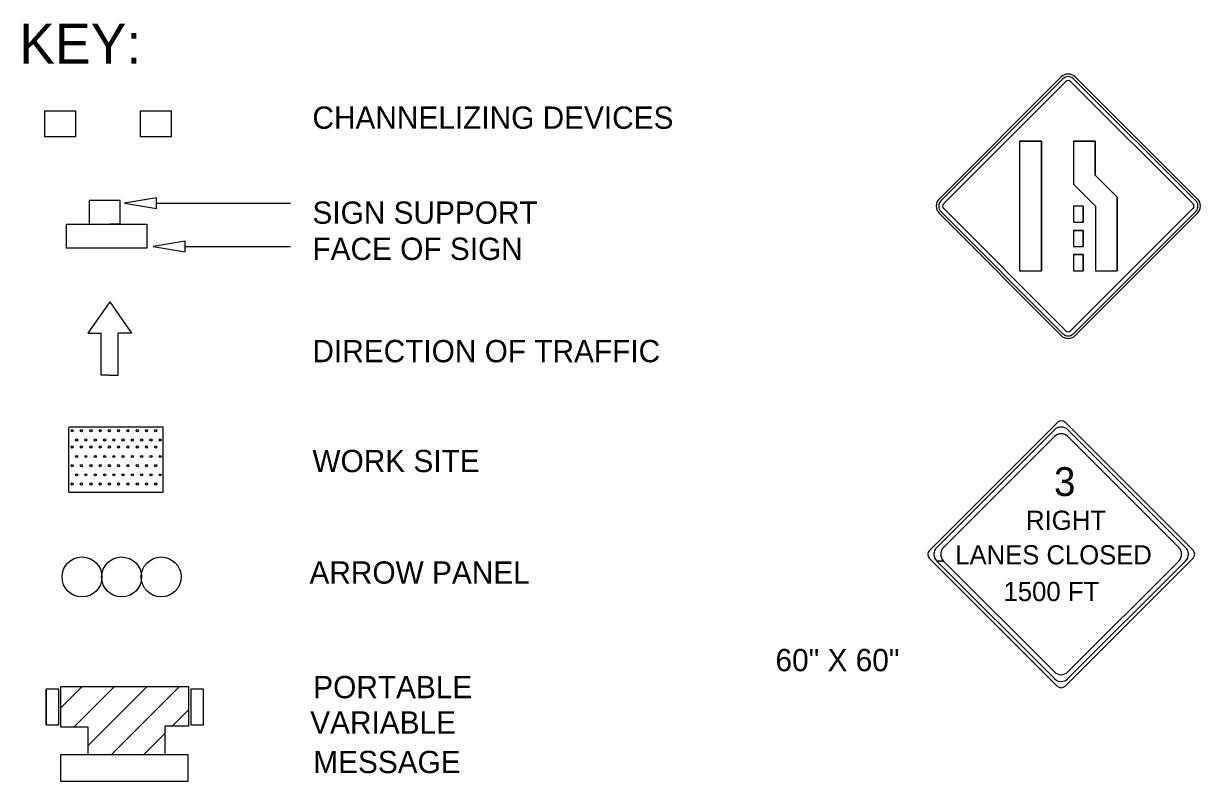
# Model space of a CAD drawing. Extents: x 1531.88 to 1538.58, y 1529.59 to 1539.31.
# Drawn here: x 1531.885 to 1535.053, y 1533.478 to 1535.518 of the extents above; entities that cross this region are included whole.
import ezdxf

# ---------------------------------------------------------------- set-up
doc = ezdxf.new("R2010")
doc.units = 0
for name, color, linetype in [('DETL-DIMS', 7, 'Continuous'), ('DETL-LINE', 7, 'Continuous'), ('DETL-NOTE', 7, 'Continuous'), ('DETL-TITL', 7, 'Continuous'), ('USER-BORD', 7, 'Continuous')]:
    doc.layers.add(name, color=color, linetype=linetype)

# ---------------------------------------------------------------- blocks, each defined once
blk = doc.blocks.new('PANEL0')
at = {"layer": 'USER-BORD'}
for centre in [(0.0309, -0.0012), (0.0928, -0.0012), (0.1546, -0.0012)]:
    blk.add_circle(centre, 0.0312, dxfattribs=at)
blk = doc.blocks.new('DIR2')
at = {"layer": 'USER-BORD'}
for p, q in [((0, 0.0012), (-0.0342, -0.0477)), ((0, 0.0012), (0.0342, -0.0477)), ((-0.0342, -0.0477), (-0.0132, -0.0477)), ((-0.0132, -0.1133), (-0.0132, -0.0477)), ((0.0342, -0.0477), (0.0132, -0.0477)), ((0.0132, -0.1133), (0.0132, -0.0477)), ((-0.0011, -0.1133), (-0.0132, -0.1133)), ((-0.0011, -0.1133), (0.0011, -0.1133)), ((0.0011, -0.1133), (0.0132, -0.1133))]:
    blk.add_line(p, q, dxfattribs=at)
blk = doc.blocks.new('SIGN13')
at = {"layer": 'USER-BORD'}
for points in [[(-0.0134, 0.0182), (0.011, 0.0189), (0.011, 0.0371), (-0.0134, 0.0371)], [(-0.0314, 0.0182), (-0.0314, 0), (0.032, 0), (0.032, 0.0182)]]:
    blk.add_lwpolyline(points, close=True, dxfattribs=at)

msp = doc.modelspace()

# ---------------------------------------------------------------- linework, layer by layer
at = {"layer": 'DETL-DIMS'}
for p, q in [((1532.2428, 1535.0342), (1532.6038, 1535.0342)), ((1532.3199, 1534.9175), (1532.6038, 1534.9175))]:
    msp.add_line(p, q, dxfattribs=at)
for points in [[(1532.2428, 1535.0198), (1532.2428, 1535.0485), (1532.1567, 1535.0342)], [(1532.3199, 1534.9031), (1532.3199, 1534.9319), (1532.2338, 1534.9175)]]:
    msp.add_lwpolyline(points, close=True, dxfattribs=at)
at = {"layer": 'DETL-LINE'}
for p, q in [((1534.3495, 1535.0455), (1534.678, 1535.3741)), ((1534.3543, 1535.0407), (1534.6829, 1535.3692)), ((1534.3619, 1535.0331), (1534.6905, 1535.3616)), ((1534.7036, 1535.3616), (1535.0328, 1535.0331)), ((1534.7112, 1535.3692), (1535.0405, 1535.0407)), ((1534.7161, 1535.3741), (1535.0453, 1535.0455)), ((1534.5663, 1535.2009), (1534.5663, 1534.8522)), ((1534.5663, 1535.2009), (1534.6249, 1535.2009)), ((1534.6249, 1535.2009), (1534.5663, 1535.2009)), ((1534.5663, 1535.2009), (1534.5663, 1534.8522)), ((1534.6249, 1535.2009), (1534.6249, 1534.8522)), ((1534.6249, 1534.8522), (1534.6249, 1535.2009)), ((1534.7114, 1535.2009), (1534.7114, 1535.0858)), ((1534.7114, 1535.2009), (1534.77, 1535.2009)), ((1534.77, 1535.2009), (1534.7114, 1535.2009)), ((1534.7114, 1535.2009), (1534.7114, 1535.0858)), ((1534.77, 1535.2009), (1534.77, 1535.11)), ((1534.77, 1535.11), (1534.77, 1535.2009)), ((1534.8292, 1535.0508), (1534.77, 1535.11)), ((1534.8292, 1535.0508), (1534.77, 1535.11)), ((1534.7706, 1535.0265), (1534.7114, 1535.0858)), ((1534.7114, 1535.0858), (1534.7706, 1535.0265)), ((1534.8292, 1535.0508), (1534.8292, 1534.8522)), ((1534.8292, 1534.8522), (1534.8292, 1535.0508)), ((1534.6829, 1534.6831), (1534.3543, 1535.0123)), ((1534.6905, 1534.6907), (1534.3619, 1535.0199)), ((1535.0328, 1535.0199), (1534.7036, 1534.6907)), ((1535.0405, 1535.0123), (1534.7112, 1534.6831)), ((1534.7114, 1535.0265), (1534.7114, 1534.9829)), ((1534.7373, 1535.0265), (1534.7114, 1535.0265)), ((1534.7114, 1535.0265), (1534.7114, 1534.9829)), ((1534.7373, 1535.0265), (1534.7373, 1534.9829)), ((1534.7373, 1534.9829), (1534.7373, 1535.0265)), ((1534.7706, 1535.0265), (1534.7706, 1534.8522)), ((1534.7706, 1535.0265), (1534.7706, 1534.8522)), ((1534.678, 1534.6783), (1534.3495, 1535.0075)), ((1534.7114, 1534.9829), (1534.7373, 1534.9829)), ((1534.7114, 1534.9829), (1534.7373, 1534.9829)), ((1535.0453, 1535.0075), (1534.7161, 1534.6783)), ((1534.7114, 1534.9611), (1534.7373, 1534.9611)), ((1534.7114, 1534.9611), (1534.7114, 1534.9176)), ((1534.7373, 1534.9611), (1534.7114, 1534.9611)), ((1534.7114, 1534.9611), (1534.7114, 1534.9176)), ((1534.7373, 1534.9611), (1534.7373, 1534.9176)), ((1534.7373, 1534.9176), (1534.7373, 1534.9611)), ((1534.7114, 1534.9176), (1534.7373, 1534.9176)), ((1534.7114, 1534.9176), (1534.7373, 1534.9176)), ((1534.7114, 1534.8958), (1534.7373, 1534.8958)), ((1534.7114, 1534.8958), (1534.7114, 1534.8522)), ((1534.7373, 1534.8958), (1534.7114, 1534.8958)), ((1534.7114, 1534.8958), (1534.7114, 1534.8522)), ((1534.7373, 1534.8958), (1534.7373, 1534.8522)), ((1534.7373, 1534.8522), (1534.7373, 1534.8958)), ((1534.5663, 1534.8522), (1534.6249, 1534.8522)), ((1534.5663, 1534.8522), (1534.6249, 1534.8522)), ((1534.7114, 1534.8522), (1534.7373, 1534.8522)), ((1534.7114, 1534.8522), (1534.7373, 1534.8522)), ((1534.7706, 1534.8522), (1534.8292, 1534.8522)), ((1534.7706, 1534.8522), (1534.8292, 1534.8522)), ((1534.6682, 1534.4439), (1534.3239, 1534.0996)), ((1535.0331, 1534.1003), (1534.6896, 1534.4439)), ((1532.2605, 1534.431), (1532.0065, 1534.431)), ((1532.2605, 1534.431), (1532.0065, 1534.431)), ((1532.2605, 1534.431), (1532.0065, 1534.431)), ((1532.2605, 1534.431), (1532.0065, 1534.431)), ((1532.0066, 1534.2569), (1532.0066, 1534.4309)), ((1532.0066, 1534.2569), (1532.0066, 1534.4309)), ((1532.0151, 1534.4221), (1532.0151, 1534.4221)), ((1532.0159, 1534.4221), (1532.0159, 1534.4221)), ((1532.0407, 1534.4221), (1532.0407, 1534.4221)), ((1532.0407, 1534.4221), (1532.0407, 1534.4221)), ((1532.0655, 1534.4221), (1532.0655, 1534.4221)), ((1532.0663, 1534.4221), (1532.0663, 1534.4221)), ((1532.0903, 1534.4221), (1532.0903, 1534.4221)), ((1532.0911, 1534.4221), (1532.0911, 1534.4221)), ((1532.1151, 1534.4221), (1532.1151, 1534.4221)), ((1532.1159, 1534.4221), (1532.1159, 1534.4221)), ((1532.1407, 1534.4221), (1532.1407, 1534.4221)), ((1532.1407, 1534.4221), (1532.1407, 1534.4221)), ((1532.1655, 1534.4221), (1532.1655, 1534.4221)), ((1532.1655, 1534.4221), (1532.1655, 1534.4221)), ((1532.1903, 1534.4221), (1532.1903, 1534.4221)), ((1532.1911, 1534.4221), (1532.1911, 1534.4221)), ((1532.2151, 1534.4221), (1532.2151, 1534.4221)), ((1532.2159, 1534.4221), (1532.2159, 1534.4221)), ((1532.2407, 1534.4221), (1532.2407, 1534.4221)), ((1532.2407, 1534.4221), (1532.2407, 1534.4221)), ((1532.2605, 1534.257), (1532.2605, 1534.431)), ((1532.2605, 1534.257), (1532.2605, 1534.431)), ((1532.2605, 1534.257), (1532.2605, 1534.431)), ((1532.2605, 1534.257), (1532.2605, 1534.431)), ((1534.6599, 1534.4243), (1534.3432, 1534.1076)), ((1535.013, 1534.1076), (1534.6964, 1534.4243)), ((1532.0151, 1534.3783), (1532.0151, 1534.3783)), ((1532.0159, 1534.3783), (1532.0159, 1534.3783)), ((1532.0279, 1534.3973), (1532.0279, 1534.3973)), ((1532.0279, 1534.3973), (1532.0279, 1534.3973)), ((1532.0407, 1534.3783), (1532.0407, 1534.3783)), ((1532.0407, 1534.3783), (1532.0407, 1534.3783)), ((1532.0527, 1534.3973), (1532.0527, 1534.3973)), ((1532.0527, 1534.3973), (1532.0527, 1534.3973)), ((1532.0655, 1534.3783), (1532.0655, 1534.3783)), ((1532.0663, 1534.3783), (1532.0663, 1534.3783)), ((1532.0783, 1534.3973), (1532.0783, 1534.3973)), ((1532.0783, 1534.3973), (1532.0783, 1534.3973)), ((1532.0903, 1534.3783), (1532.0903, 1534.3783)), ((1532.0911, 1534.3783), (1532.0911, 1534.3783)), ((1532.1031, 1534.3973), (1532.1031, 1534.3973)), ((1532.1031, 1534.3973), (1532.1031, 1534.3973)), ((1532.1151, 1534.3783), (1532.1151, 1534.3783)), ((1532.1159, 1534.3783), (1532.1159, 1534.3783)), ((1532.1279, 1534.3973), (1532.1279, 1534.3973)), ((1532.1279, 1534.3973), (1532.1279, 1534.3973)), ((1532.1407, 1534.3783), (1532.1407, 1534.3783)), ((1532.1407, 1534.3783), (1532.1407, 1534.3783)), ((1532.1527, 1534.3973), (1532.1527, 1534.3973)), ((1532.1527, 1534.3973), (1532.1527, 1534.3973)), ((1532.1655, 1534.3783), (1532.1655, 1534.3783)), ((1532.1655, 1534.3783), (1532.1655, 1534.3783)), ((1532.1775, 1534.3973), (1532.1775, 1534.3973)), ((1532.1775, 1534.3973), (1532.1775, 1534.3973)), ((1532.1903, 1534.3783), (1532.1903, 1534.3783)), ((1532.1911, 1534.3783), (1532.1911, 1534.3783)), ((1532.2031, 1534.3973), (1532.2031, 1534.3973)), ((1532.2031, 1534.3973), (1532.2031, 1534.3973)), ((1532.2151, 1534.3783), (1532.2151, 1534.3783)), ((1532.2159, 1534.3783), (1532.2159, 1534.3783)), ((1532.2279, 1534.3973), (1532.2279, 1534.3973)), ((1532.2279, 1534.3973), (1532.2279, 1534.3973)), ((1532.2407, 1534.3783), (1532.2407, 1534.3783)), ((1532.2407, 1534.3783), (1532.2407, 1534.3783)), ((1532.2527, 1534.3973), (1532.2527, 1534.3973)), ((1532.2527, 1534.3973), (1532.2527, 1534.3973)), ((1534.3614, 1534.1077), (1534.6598, 1534.406)), ((1534.6964, 1534.406), (1534.9948, 1534.1076)), ((1532.0279, 1534.3527), (1532.0279, 1534.3527)), ((1532.0527, 1534.3527), (1532.0527, 1534.3527)), ((1532.0783, 1534.3527), (1532.0783, 1534.3527)), ((1532.1031, 1534.3527), (1532.1031, 1534.3527)), ((1532.1279, 1534.3527), (1532.1279, 1534.3527)), ((1532.1527, 1534.3527), (1532.1527, 1534.3527)), ((1532.1775, 1534.3527), (1532.1775, 1534.3527)), ((1532.2031, 1534.3527), (1532.2031, 1534.3527)), ((1532.2279, 1534.3527), (1532.2279, 1534.3527)), ((1532.2527, 1534.3527), (1532.2527, 1534.3527)), ((1532.0151, 1534.3279), (1532.0151, 1534.3279)), ((1532.0159, 1534.3279), (1532.0159, 1534.3279)), ((1532.0407, 1534.3279), (1532.0407, 1534.3279)), ((1532.0407, 1534.3279), (1532.0407, 1534.3279)), ((1532.0655, 1534.3279), (1532.0655, 1534.3279)), ((1532.0663, 1534.3279), (1532.0663, 1534.3279)), ((1532.0903, 1534.3279), (1532.0903, 1534.3279)), ((1532.0911, 1534.3279), (1532.0911, 1534.3279)), ((1532.1151, 1534.3279), (1532.1151, 1534.3279)), ((1532.1159, 1534.3279), (1532.1159, 1534.3279)), ((1532.1407, 1534.3279), (1532.1407, 1534.3279)), ((1532.1407, 1534.3279), (1532.1407, 1534.3279)), ((1532.1655, 1534.3279), (1532.1655, 1534.3279)), ((1532.1655, 1534.3279), (1532.1655, 1534.3279)), ((1532.1903, 1534.3279), (1532.1903, 1534.3279)), ((1532.1911, 1534.3279), (1532.1911, 1534.3279)), ((1532.2151, 1534.3279), (1532.2151, 1534.3279)), ((1532.2159, 1534.3279), (1532.2159, 1534.3279)), ((1532.2407, 1534.3279), (1532.2407, 1534.3279)), ((1532.2407, 1534.3279), (1532.2407, 1534.3279)), ((1532.0279, 1534.3031), (1532.0279, 1534.3031)), ((1532.0279, 1534.3031), (1532.0279, 1534.3031)), ((1532.0527, 1534.3031), (1532.0527, 1534.3031)), ((1532.0527, 1534.3031), (1532.0527, 1534.3031)), ((1532.0783, 1534.3031), (1532.0783, 1534.3031)), ((1532.0783, 1534.3031), (1532.0783, 1534.3031)), ((1532.1031, 1534.3031), (1532.1031, 1534.3031)), ((1532.1031, 1534.3031), (1532.1031, 1534.3031)), ((1532.1279, 1534.3031), (1532.1279, 1534.3031)), ((1532.1279, 1534.3031), (1532.1279, 1534.3031)), ((1532.1527, 1534.3031), (1532.1527, 1534.3031)), ((1532.1527, 1534.3031), (1532.1527, 1534.3031)), ((1532.1775, 1534.3031), (1532.1775, 1534.3031)), ((1532.1775, 1534.3031), (1532.1775, 1534.3031)), ((1532.2031, 1534.3031), (1532.2031, 1534.3031)), ((1532.2031, 1534.3031), (1532.2031, 1534.3031)), ((1532.2279, 1534.3031), (1532.2279, 1534.3031)), ((1532.2279, 1534.3031), (1532.2279, 1534.3031)), ((1532.2527, 1534.3031), (1532.2527, 1534.3031)), ((1532.2527, 1534.3031), (1532.2527, 1534.3031)), ((1532.0066, 1534.2569), (1532.2606, 1534.2569)), ((1532.0151, 1534.2787), (1532.0151, 1534.2787)), ((1532.0159, 1534.2787), (1532.0159, 1534.2787)), ((1532.0407, 1534.2787), (1532.0407, 1534.2787)), ((1532.0407, 1534.2787), (1532.0407, 1534.2787)), ((1532.0655, 1534.2787), (1532.0655, 1534.2787)), ((1532.0663, 1534.2787), (1532.0663, 1534.2787)), ((1532.0903, 1534.2787), (1532.0903, 1534.2787)), ((1532.0911, 1534.2787), (1532.0911, 1534.2787)), ((1532.1151, 1534.2787), (1532.1151, 1534.2787)), ((1532.1159, 1534.2787), (1532.1159, 1534.2787)), ((1532.1407, 1534.2787), (1532.1407, 1534.2787)), ((1532.1407, 1534.2787), (1532.1407, 1534.2787)), ((1532.1655, 1534.2787), (1532.1655, 1534.2787)), ((1532.1655, 1534.2787), (1532.1655, 1534.2787)), ((1532.1903, 1534.2787), (1532.1903, 1534.2787)), ((1532.1911, 1534.2787), (1532.1911, 1534.2787)), ((1532.2151, 1534.2787), (1532.2151, 1534.2787)), ((1532.2159, 1534.2787), (1532.2159, 1534.2787)), ((1532.2407, 1534.2787), (1532.2407, 1534.2787)), ((1532.2407, 1534.2787), (1532.2407, 1534.2787)), ((1534.3239, 1534.0783), (1534.6675, 1533.7347)), ((1534.3614, 1534.0711), (1534.3432, 1534.0711)), ((1534.3432, 1534.0711), (1534.6599, 1533.7545)), ((1534.3432, 1534.0711), (1534.3614, 1534.0711)), ((1534.6598, 1533.7727), (1534.3614, 1534.0711)), ((1534.6888, 1533.7347), (1535.0331, 1534.079)), ((1534.6964, 1533.7545), (1535.013, 1534.0711)), ((1534.9948, 1534.0711), (1534.6964, 1533.7727)), ((1534.6598, 1533.7727), (1534.6598, 1533.7727)), ((1531.9462, 1533.6301), (1531.9462, 1533.7259)), ((1531.9462, 1533.7259), (1531.9462, 1533.6301)), ((1531.9798, 1533.7259), (1531.9462, 1533.7259)), ((1531.9462, 1533.7259), (1531.9462, 1533.6301)), ((1531.9798, 1533.6301), (1531.9798, 1533.7259)), ((1531.9852, 1533.6762), (1532.0426, 1533.7337)), ((1531.9852, 1533.6243), (1531.9852, 1533.7337)), ((1531.9868, 1533.7337), (1532.3289, 1533.7337)), ((1532.0207, 1533.6243), (1532.13, 1533.7337)), ((1532.0587, 1533.575), (1532.2174, 1533.7337)), ((1532.1217, 1533.5506), (1532.3048, 1533.7337)), ((1532.3289, 1533.7337), (1532.3289, 1533.6262)), ((1532.3689, 1533.7259), (1532.3353, 1533.7259)), ((1532.3353, 1533.7259), (1532.3353, 1533.6301)), ((1532.3689, 1533.6301), (1532.3689, 1533.7259)), ((1532.2848, 1533.6263), (1532.3289, 1533.6705)), ((1531.9462, 1533.6301), (1531.9798, 1533.6301)), ((1532.0587, 1533.6243), (1531.9852, 1533.6243)), ((1532.0587, 1533.5501), (1532.0587, 1533.6243)), ((1532.265, 1533.6262), (1532.265, 1533.5501)), ((1532.3289, 1533.6262), (1532.265, 1533.6262)), ((1532.3353, 1533.6301), (1532.3689, 1533.6301)), ((1532.2091, 1533.5506), (1532.265, 1533.6065)), ((1531.9852, 1533.5501), (1532.3274, 1533.5501)), ((1531.9852, 1533.4778), (1531.9852, 1533.5501)), ((1532.3274, 1533.5501), (1532.3274, 1533.4778)), ((1532.3274, 1533.4778), (1531.9852, 1533.4778))]:
    msp.add_line(p, q, dxfattribs=at)
for points in [[(1531.9423, 1535.2131), (1531.9423, 1535.2826), (1532.0249, 1535.2826), (1532.0249, 1535.2131)], [(1532.1994, 1535.2131), (1532.1994, 1535.2826), (1532.2819, 1535.2826), (1532.2819, 1535.2131)]]:
    msp.add_lwpolyline(points, close=True, dxfattribs=at)
for centre in [(1532.0159, 1534.4219), (1532.0407, 1534.4219), (1532.0663, 1534.4219), (1532.0911, 1534.4219), (1532.1159, 1534.4219), (1532.1407, 1534.4219), (1532.1655, 1534.4219), (1532.1911, 1534.4219), (1532.2159, 1534.4219), (1532.2407, 1534.4219), (1532.0159, 1534.3782), (1532.0279, 1534.3971), (1532.0407, 1534.3782), (1532.0527, 1534.3971), (1532.0663, 1534.3782), (1532.0783, 1534.3971), (1532.0911, 1534.3782), (1532.1031, 1534.3971), (1532.1159, 1534.3782), (1532.1279, 1534.3971), (1532.1407, 1534.3782), (1532.1527, 1534.3971), (1532.1655, 1534.3782), (1532.1775, 1534.3971), (1532.1911, 1534.3782), (1532.2031, 1534.3971), (1532.2159, 1534.3782), (1532.2279, 1534.3971), (1532.2407, 1534.3782), (1532.2527, 1534.3971), (1532.0279, 1534.3526), (1532.0527, 1534.3526), (1532.0783, 1534.3526), (1532.1031, 1534.3526), (1532.1279, 1534.3526), (1532.1527, 1534.3526), (1532.1775, 1534.3526), (1532.2031, 1534.3526), (1532.2279, 1534.3526), (1532.2527, 1534.3526), (1532.0159, 1534.3278), (1532.0407, 1534.3278), (1532.0663, 1534.3278), (1532.0911, 1534.3278), (1532.1159, 1534.3278), (1532.1407, 1534.3278), (1532.1655, 1534.3278), (1532.1911, 1534.3278), (1532.2159, 1534.3278), (1532.2407, 1534.3278), (1532.0159, 1534.2786), (1532.0279, 1534.303), (1532.0407, 1534.2786), (1532.0527, 1534.303), (1532.0663, 1534.2786), (1532.0783, 1534.303), (1532.0911, 1534.2786), (1532.1031, 1534.303), (1532.1159, 1534.2786), (1532.1279, 1534.303), (1532.1407, 1534.2786), (1532.1527, 1534.303), (1532.1655, 1534.2786), (1532.1775, 1534.303), (1532.1911, 1534.2786), (1532.2031, 1534.303), (1532.2159, 1534.2786), (1532.2279, 1534.303), (1532.2407, 1534.2786), (1532.2527, 1534.303)]:
    msp.add_circle(centre, 0.00291, dxfattribs=at)
for centre, radius, start, end in [((1534.697, 1535.3549), 0.027, 45.06, 135), ((1534.697, 1535.3553), 0.0199, 45.06, 135), ((1534.697, 1535.3555), 0.00901, 45.06, 135), ((1534.3687, 1535.0265), 0.027, 135, 224.9399), ((1535.0261, 1535.0265), 0.027, 315, 45.0601), ((1534.3683, 1535.0265), 0.0199, 135, 224.9399), ((1534.3681, 1535.0265), 0.00901, 135, 224.9399), ((1535.0267, 1535.0265), 0.00901, 315, 45.0601), ((1535.0265, 1535.0265), 0.0199, 315, 45.0601), ((1534.697, 1534.6974), 0.027, 224.94, 315), ((1534.697, 1534.697), 0.0199, 224.94, 315), ((1534.697, 1534.6969), 0.00901, 224.94, 315), ((1534.6789, 1534.4333), 0.0151, 45, 135), ((1534.6781, 1534.3878), 0.0258, 45, 135), ((1534.6781, 1534.406), 0.0258, 45, 135), ((1534.3345, 1534.0889), 0.0151, 135, 225), ((1534.3615, 1534.0894), 0.0258, 135, 225), ((1534.3797, 1534.0894), 0.0258, 135, 225), ((1534.9765, 1534.0894), 0.0258, 315, 45), ((1534.9948, 1534.0894), 0.0258, 315, 45), ((1535.0225, 1534.0897), 0.0151, 315, 45), ((1534.6781, 1533.791), 0.0258, 225, 315), ((1534.6781, 1533.7727), 0.0258, 225, 315), ((1534.6781, 1533.7453), 0.0151, 225, 315)]:
    msp.add_arc(centre, radius, start, end, dxfattribs=at)

# ---------------------------------------------------------------- block references
for name, p, xscale, yscale in [('SIGN13', (1532.1074, 1534.9141), 3.4447058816, 3.4447058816), ('DIR2', (1532.1168, 1534.7667), 1.7223529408, 1.7223529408), ('PANEL0', (1531.9891, 1534.0303), 1.7223529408, 1.7223529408)]:
    msp.add_blockref(name, p, dxfattribs=dict(at, xscale=xscale, yscale=yscale))

# ---------------------------------------------------------------- texts
for s, height, p in [('3', 0.0775, (1534.6589, 1534.2461)), ('RIGHT', 0.05184, (1534.5834, 1534.1549)), ('LANES CLOSED', 0.051584, (1534.3932, 1534.0621)), ('1500 FT', 0.05176, (1534.5229, 1533.9633))]:
    msp.add_text(s, height=height, dxfattribs=at).set_placement(p)
at = {"layer": 'DETL-NOTE'}
for s, p in [('CHANNELIZING DEVICES', (1532.6626, 1535.2346)), ('SIGN SUPPORT', (1532.6626, 1534.9789)), ('FACE OF SIGN', (1532.6626, 1534.8815)), ('DIRECTION OF TRAFFIC', (1532.6626, 1534.6062)), ('WORK SITE', (1532.6626, 1534.3104)), ('ARROW PANEL', (1532.6547, 1534.0102)), ('60" X 60"', (1533.9092, 1533.7745)), ('PORTABLE', (1532.6648, 1533.7018)), ('VARIABLE', (1532.6566, 1533.6065)), ('MESSAGE', (1532.6648, 1533.5002))]:
    msp.add_text(s, height=0.06, dxfattribs=at).set_placement(p)
at = {"layer": 'DETL-TITL'}
msp.add_text('KEY:', height=0.108, dxfattribs=at).set_placement((1531.873, 1535.4099))

doc.saveas('drawing.dxf')
